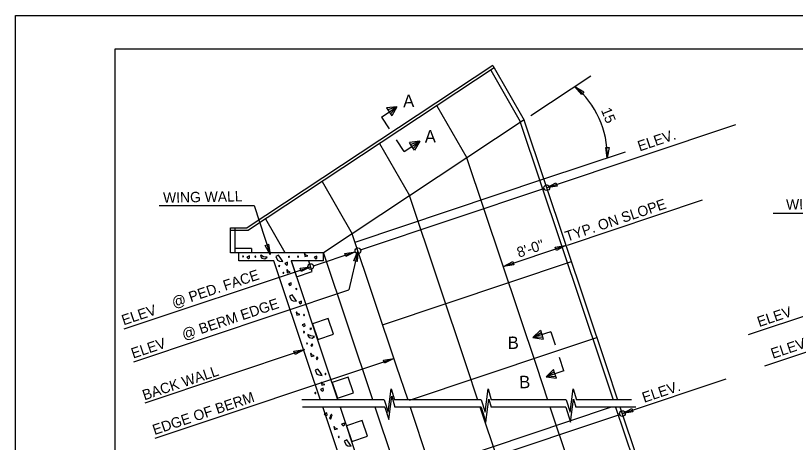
# Model space of a CAD drawing. Extents: x 0 to 272, y 0 to 188.
# Drawn here: x 0 to 94, y 124.5 to 176 of the extents above; entities that cross this region are included whole.
import ezdxf

# ---------------------------------------------------------------- set-up
doc = ezdxf.new("R2010")
doc.units = 0
for name, color, linetype in [('BORDER_ANNO_Cutsheet', 7, 'Continuous'), ('BRDG_ANNO_Anno-Sheet', 7, 'Continuous'), ('BRDG_ANNO_General-Notes', 7, 'Continuous'), ('BRDG_BASE_Hidden-Line', 7, 'Continuous'), ('BRDG_BASE_Obj-Line', 7, 'Continuous'), ('BRDG_BASE_Pattern', 7, 'Continuous')]:
    doc.layers.add(name, color=color, linetype=linetype)

msp = doc.modelspace()

# ---------------------------------------------------------------- linework, layer by layer
at = {"layer": 'BORDER_ANNO_Cutsheet'}
msp.add_lwpolyline([(0, 176), (272, 176), (272, 0), (0, 0)], close=True, dxfattribs=at)
at = {"layer": 'BRDG_ANNO_Anno-Sheet'}
msp.add_lwpolyline([(12, 172), (268, 172), (268, 4), (12, 4)], close=True, dxfattribs=at)
at = {"layer": 'BRDG_ANNO_General-Notes'}
for p, q in [((69.325, 168.71), (62.09, 163.925)), ((68.243, 166.486), (67.419, 167.449)), ((67.419, 167.449), (68.51, 166.806)), ((68.51, 166.806), (68.243, 166.486)), ((44.088, 163.765), (45.97, 164.998)), ((45.97, 164.998), (44.721, 164.852)), ((44.721, 164.852), (45.029, 164.381)), ((45.97, 164.998), (44.875, 164.617)), ((45.97, 164.998), (45.184, 164.146)), ((45.97, 164.998), (45.338, 163.911)), ((44.088, 163.765), (45.014, 162.353)), ((45.029, 164.381), (45.338, 163.911)), ((64.013, 155.238), (86.825, 162.871)), ((46.84, 159.599), (45.915, 161.01)), ((46.84, 159.599), (48.721, 160.832)), ((48.721, 160.832), (47.472, 160.686)), ((48.721, 160.832), (47.626, 160.451)), ((48.721, 160.832), (47.935, 159.98)), ((48.721, 160.832), (48.089, 159.745)), ((47.781, 160.215), (47.472, 160.686)), ((48.089, 159.745), (47.781, 160.215)), ((71.134, 160.098), (71.55, 160.088)), ((71.313, 158.843), (71.134, 160.098)), ((71.55, 160.088), (71.313, 158.843)), ((63.678, 156.289), (73.506, 159.577)), ((41.586, 147.734), (63.69, 155.13)), ((64.013, 155.238), (65.132, 155.832)), ((65.265, 155.437), (64.013, 155.238)), ((65.132, 155.832), (65.265, 155.437)), ((66.528, 148.321), (82.79, 153.762)), ((17.317, 153.07), (28.741, 153.07)), ((28.741, 153.07), (30.682, 147.162)), ((91.339, 152.184), (102.763, 152.184)), ((30.094, 148.284), (30.49, 148.414)), ((30.682, 147.162), (30.094, 148.284)), ((30.49, 148.414), (30.682, 147.162)), ((41.263, 147.591), (40.18, 142.925)), ((40.778, 146.42), (41.263, 147.591)), ((41.263, 147.591), (41.184, 146.326)), ((58.815, 145.74), (66.302, 148.245)), ((65.051, 148.046), (66.302, 148.245)), ((65.183, 147.651), (65.051, 148.046)), ((66.302, 148.245), (65.183, 147.651)), ((35.895, 145.83), (40.933, 147.515)), ((39.682, 147.316), (40.933, 147.515)), ((39.814, 146.921), (39.682, 147.316)), ((40.933, 147.515), (39.814, 146.921)), ((13.085, 138.197), (35.539, 145.711)), ((34.288, 145.512), (35.539, 145.711)), ((35.539, 145.711), (34.42, 145.116)), ((41.184, 146.326), (40.778, 146.42)), ((58.815, 145.74), (59.934, 146.334)), ((60.067, 145.939), (58.815, 145.74)), ((59.934, 146.334), (60.067, 145.939)), ((34.42, 145.116), (34.288, 145.512)), ((88.352, 137.529), (111.7, 145.341)), ((14.234, 134.244), (40.18, 142.925)), ((90.304, 133.747), (114.983, 142.005)), ((62.365, 137.164), (63.256, 138.051)), ((64.501, 137.87), (62.365, 137.164)), ((62.365, 137.164), (63.344, 137.784)), ((62.365, 137.164), (63.521, 137.25)), ((63.256, 138.051), (63.433, 137.517)), ((63.433, 137.517), (63.61, 136.983)), ((64.501, 137.87), (65.031, 136.268)), ((62.365, 137.164), (63.61, 136.983)), ((15.599, 129.278), (34.807, 135.705)), ((33.555, 135.506), (34.807, 135.705)), ((33.687, 135.111), (33.555, 135.506)), ((34.807, 135.705), (33.687, 135.111)), ((16.834, 125.024), (45.601, 134.649)), ((44.349, 134.45), (45.601, 134.649)), ((44.482, 134.055), (44.349, 134.45)), ((45.601, 134.649), (44.482, 134.055)), ((66.085, 133.136), (65.555, 134.738)), ((63.949, 132.429), (64.84, 133.317)), ((66.085, 133.136), (63.949, 132.429)), ((63.949, 132.429), (64.929, 133.049)), ((65.017, 132.782), (64.84, 133.317)), ((65.194, 132.248), (65.017, 132.782)), ((63.949, 132.429), (65.105, 132.515)), ((63.949, 132.429), (65.194, 132.248)), ((73.144, 127.999), (85.647, 132.182)), ((46.932, 119.228), (72.827, 127.893)), ((73.144, 127.999), (74.263, 128.593)), ((74.396, 128.198), (73.144, 127.999)), ((74.263, 128.593), (74.396, 128.198))]:
    msp.add_line(p, q, dxfattribs=at)
for centre in [(64.024, 155.238), (41.266, 147.621), (35.572, 145.722), (73.147, 127.996)]:
    msp.add_circle(centre, 0.343, dxfattribs=at)
msp.add_arc((60.422, 159.099), 10.894, 358.65678, 50.03979, dxfattribs=at)
at = {"layer": 'BRDG_BASE_Hidden-Line'}
for p, q in [((57.276, 169.418), (60.824, 163.243)), ((70.709, 133.702), (60.824, 163.243)), ((26.41, 150.395), (26.41, 147.395)), ((28.429, 147.909), (26.429, 147.909)), ((28.429, 147.909), (28.429, 147.409)), ((43.072, 129.632), (37.125, 147.404)), ((72.081, 129.6), (70.709, 133.702)), ((57.505, 86.496), (43.358, 128.776)), ((85.925, 88.224), (72.373, 128.728))]:
    msp.add_line(p, q, dxfattribs=at)
at = {"layer": 'BRDG_BASE_Obj-Line'}
for p, q in [((57.52, 169.978), (27.91, 150.395)), ((57.686, 169.688), (28.072, 150.103)), ((57.52, 169.978), (61.299, 163.401)), ((50.777, 165.12), (54.394, 158.825)), ((61.32, 163.416), (37.097, 147.395)), ((71.254, 133.647), (61.299, 163.401)), ((43.88, 160.553), (47.472, 154.301)), ((62.813, 133.662), (54.394, 158.825)), ((40.935, 148.679), (63.678, 156.289)), ((36.96, 155.983), (40.583, 149.678)), ((54.383, 133.646), (47.472, 154.301)), ((30.142, 151.472), (32.467, 147.425)), ((25.91, 147.395), (25.91, 150.395)), ((25.91, 150.395), (27.91, 150.395)), ((25.912, 150.103), (28.072, 150.103)), ((45.922, 133.721), (40.583, 149.678)), ((37.097, 147.395), (25.91, 147.395)), ((26.91, 146.395), (26.91, 147.395)), ((37.097, 146.395), (37.097, 147.395)), ((31.11, 146.395), (26.91, 146.395)), ((35.398, 133.659), (31.133, 146.403)), ((37.097, 146.395), (33.232, 146.395)), ((33.232, 146.395), (33.874, 144.5)), ((37.486, 133.72), (33.244, 146.399)), ((35.768, 145.142), (35.352, 146.37)), ((44.33, 138.743), (67.01, 146.331)), ((33.874, 144.5), (35.768, 145.142)), ((37.676, 139.453), (35.782, 138.812)), ((38.317, 137.559), (37.676, 139.453)), ((35.782, 138.812), (36.423, 136.917)), ((36.423, 136.917), (38.317, 137.559)), ((64.642, 135.346), (70.077, 137.164)), ((47.482, 129.604), (64.642, 135.346)), ((36.751, 129.615), (35.398, 133.659)), ((38.85, 129.643), (37.486, 133.72)), ((47.304, 129.59), (45.922, 133.721)), ((55.737, 129.599), (54.383, 133.646)), ((64.173, 129.599), (62.813, 133.662)), ((72.605, 129.611), (71.254, 133.647)), ((40.074, 132.37), (38.18, 131.729)), ((38.18, 131.729), (38.821, 129.834)), ((40.715, 130.476), (40.074, 132.37)), ((44.903, 128.152), (45.278, 130.958)), ((45.278, 130.958), (45.656, 129.631)), ((56.59, 128.152), (56.962, 130.957)), ((56.962, 130.957), (57.341, 129.633)), ((66.857, 128.154), (67.229, 130.959)), ((67.229, 130.959), (67.609, 129.635)), ((38.821, 129.834), (40.715, 130.476)), ((44.979, 127.281), (45.354, 130.088)), ((45.354, 130.088), (45.732, 128.761)), ((56.693, 126.965), (57.061, 129.741)), ((57.061, 129.741), (57.341, 128.762)), ((66.893, 126.967), (67.261, 129.742)), ((67.261, 129.742), (67.541, 128.764)), ((44.425, 129.632), (34.508, 129.632)), ((40.177, 119.375), (37.025, 128.794)), ((44.425, 129.632), (44.903, 128.152)), ((46.556, 129.631), (45.656, 129.631)), ((51.953, 129.631), (46.556, 129.631)), ((56.109, 129.631), (51.953, 129.631)), ((56.109, 129.631), (56.59, 128.152)), ((66.377, 129.633), (57.341, 129.633)), ((66.377, 129.633), (66.857, 128.154)), ((74.232, 129.635), (67.609, 129.635)), ((44.501, 128.761), (34.584, 128.761)), ((42.069, 120.024), (39.155, 128.733)), ((44.501, 128.761), (44.979, 127.281)), ((46.556, 128.761), (45.732, 128.761)), ((51.953, 128.761), (46.556, 128.761)), ((61.713, 86.525), (47.591, 128.731)), ((50.015, 121.488), (71.723, 128.752)), ((56.109, 128.761), (51.953, 128.761)), ((70.146, 86.534), (56.014, 128.772)), ((56.109, 128.761), (56.693, 126.965)), ((66.309, 128.763), (57.341, 128.762)), ((78.007, 88.253), (64.448, 128.776)), ((66.309, 128.763), (66.893, 126.967)), ((74.776, 128.765), (67.541, 128.764)), ((86.434, 88.278), (72.883, 128.778)), ((41.778, 127.156), (39.884, 126.515)), ((42.419, 125.262), (41.778, 127.156)), ((39.884, 126.515), (40.525, 124.621)), ((40.525, 124.621), (42.419, 125.262))]:
    msp.add_line(p, q, dxfattribs=at)
at = {"layer": 'BRDG_BASE_Pattern'}
for points in [[(27.36, 146.973), (27.389, 146.897), (27.445, 146.897), (27.478, 146.93), (27.478, 146.959), (27.45, 146.987), (27.431, 146.996), (27.402, 146.996)], [(27.869, 146.877), (28.06, 146.666), (28.21, 146.76), (28.192, 147.013)], [(28.842, 146.939), (28.87, 146.863), (28.926, 146.863), (28.959, 146.897), (28.959, 146.926), (28.931, 146.954), (28.912, 146.962), (28.883, 146.962)], [(29.525, 146.982), (29.694, 146.729), (30.041, 146.664), (30.322, 146.851), (29.886, 146.913), (29.549, 147.09)], [(31.357, 146.948), (31.583, 146.496), (31.808, 146.384), (32.202, 146.328), (31.977, 146.703), (31.695, 147.098)], [(32.882, 146.939), (32.91, 146.863), (32.966, 146.863), (32.999, 146.897), (32.999, 146.926), (32.971, 146.954), (32.952, 146.962), (32.923, 146.962)], [(33.993, 146.939), (34.021, 146.863), (34.077, 146.863), (34.11, 146.897), (34.11, 146.926), (34.082, 146.954), (34.063, 146.962), (34.034, 146.962)], [(34.81, 147.256), (34.876, 146.929), (35.228, 147.017), (34.97, 147.116), (34.839, 147.313)], [(35.983, 146.843), (36.174, 146.633), (36.324, 146.727), (36.306, 146.979)], [(31.678, 145.818), (31.828, 145.705), (31.865, 145.856)], [(32.447, 146.102), (32.639, 145.892), (32.789, 145.986), (32.771, 146.239)], [(32.208, 144.986), (32.237, 144.911), (32.293, 144.911), (32.326, 144.944), (32.326, 144.973), (32.298, 145.001), (32.279, 145.01), (32.25, 145.01)], [(32.689, 145.304), (32.755, 144.976), (33.107, 145.065), (32.849, 145.163), (32.718, 145.36)], [(32.885, 143.645), (33.076, 143.434), (33.226, 143.528), (33.208, 143.781)], [(33.731, 143.057), (33.881, 142.944), (33.919, 143.096)], [(33.007, 142.167), (33.233, 141.715), (33.458, 141.603), (33.852, 141.547), (33.627, 141.922), (33.345, 142.317)], [(34.131, 141.423), (34.322, 141.212), (34.472, 141.306), (34.454, 141.559)], [(33.834, 140.186), (33.9, 139.859), (34.252, 139.947), (33.994, 140.046), (33.863, 140.243)], [(34.7, 139.903), (34.728, 139.827), (34.784, 139.827), (34.817, 139.86), (34.817, 139.889), (34.789, 139.917), (34.77, 139.926), (34.741, 139.926)], [(34.556, 138.697), (34.747, 138.487), (34.897, 138.581), (34.879, 138.834)], [(35.482, 138.243), (35.632, 138.13), (35.67, 138.281)], [(34.685, 137.819), (34.755, 137.749), (34.811, 137.757), (34.811, 137.777), (34.811, 137.833), (34.792, 137.889), (34.76, 137.894), (34.732, 137.884), (34.722, 137.876), (34.709, 137.852)], [(35.214, 137.421), (35.384, 137.167), (35.731, 137.103), (36.012, 137.29), (35.576, 137.352), (35.238, 137.528)], [(35.07, 136.469), (35.098, 136.393), (35.155, 136.393), (35.187, 136.426), (35.187, 136.455), (35.159, 136.483), (35.141, 136.492), (35.112, 136.492)], [(35.6, 136.206), (35.693, 136.075), (35.806, 136.225), (35.825, 136.282), (35.732, 136.412)], [(35.554, 135.201), (35.62, 134.873), (35.972, 134.962), (35.714, 135.06), (35.583, 135.257)], [(36.225, 134.621), (36.319, 134.491), (36.431, 134.641), (36.45, 134.697), (36.357, 134.828)], [(36.104, 133.212), (36.33, 132.76), (36.555, 132.648), (36.949, 132.592), (36.724, 132.967), (36.442, 133.362)], [(37.277, 132.769), (37.348, 132.699), (37.403, 132.707), (37.403, 132.727), (37.403, 132.783), (37.384, 132.839), (37.352, 132.844), (37.324, 132.834), (37.314, 132.826), (37.301, 132.802)], [(36.854, 131.734), (36.92, 131.407), (37.272, 131.495), (37.014, 131.594), (36.883, 131.791)], [(36.77, 130.902), (36.961, 130.691), (37.111, 130.786), (37.093, 131.038)], [(36.057, 130.462), (36.127, 130.391), (36.183, 130.4), (36.183, 130.419), (36.183, 130.475), (36.164, 130.532), (36.132, 130.536), (36.103, 130.526), (36.094, 130.518), (36.081, 130.494)], [(37.201, 127.926), (37.392, 127.716), (37.542, 127.81), (37.524, 128.063)], [(37.933, 127.693), (38.027, 127.562), (38.139, 127.712), (38.158, 127.769), (38.065, 127.899)], [(37.847, 127.434), (37.941, 127.303), (38.053, 127.453), (38.072, 127.51), (37.979, 127.641)], [(38.369, 126.381), (38.435, 126.054), (38.787, 126.142), (38.529, 126.241), (38.398, 126.438)], [(39.303, 126.712), (39.494, 126.501), (39.644, 126.596), (39.627, 126.848)], [(38.893, 125.161), (38.964, 125.09), (39.019, 125.099), (39.019, 125.118), (39.019, 125.174), (39, 125.231), (38.968, 125.235), (38.94, 125.225), (38.93, 125.217), (38.917, 125.193)], [(39.606, 124.661), (39.831, 124.209), (40.057, 124.097), (40.45, 124.041), (40.225, 124.416), (39.944, 124.81)]]:
    msp.add_lwpolyline(points, close=True, dxfattribs=at)

# ---------------------------------------------------------------- texts
at = {"layer": 'BRDG_ANNO_General-Notes'}
for s, height, rotation, p in [('A', 1.5, 1.1, (46.73, 164.948)), ('15', 1.25, 291.80147, (70.545, 164.607)), ('A', 1.5, 1.1, (49.329, 160.666)), ('ELEV.', 1.25, 18.49994, (75.224, 159.608)), ('WING WALL', 1.25, 1.1, (17.794, 153.41)), ('8\'-0"      TYP. ON SLOPE', 1.25, 18.49992, (60.674, 146.782)), ('WING WALL', 1.25, 1.1, (92.89, 152.586)), ('@ PED. FACE', 1.25, 18.49992, (19.066, 140.729)), ('ELEV  ', 1.25, 18.49992, (13.025, 138.621)), ('@ BERM EDGE', 1.25, 18.49992, (20.288, 136.878)), ('ELEV  ', 1.25, 18.49992, (89.637, 138.416)), ('B', 1.5, 1.1, (59.33, 135.777)), ('ELEV  ', 1.25, 18.49992, (14.173, 134.616)), ('ELEV  ', 1.25, 18.49992, (91.289, 134.595)), ('BACK WALL', 1.25, 18.49994, (15.534, 129.578)), ('B', 1.5, 1.1, (60.716, 131.037)), ('ELEV.', 1.25, 18.49994, (75.77, 129.285)), ('EDGE OF BERM', 1.25, 18.49991, (16.748, 125.392))]:
    msp.add_text(s, height=height, rotation=rotation, dxfattribs=at).set_placement(p)

doc.saveas('drawing.dxf')
